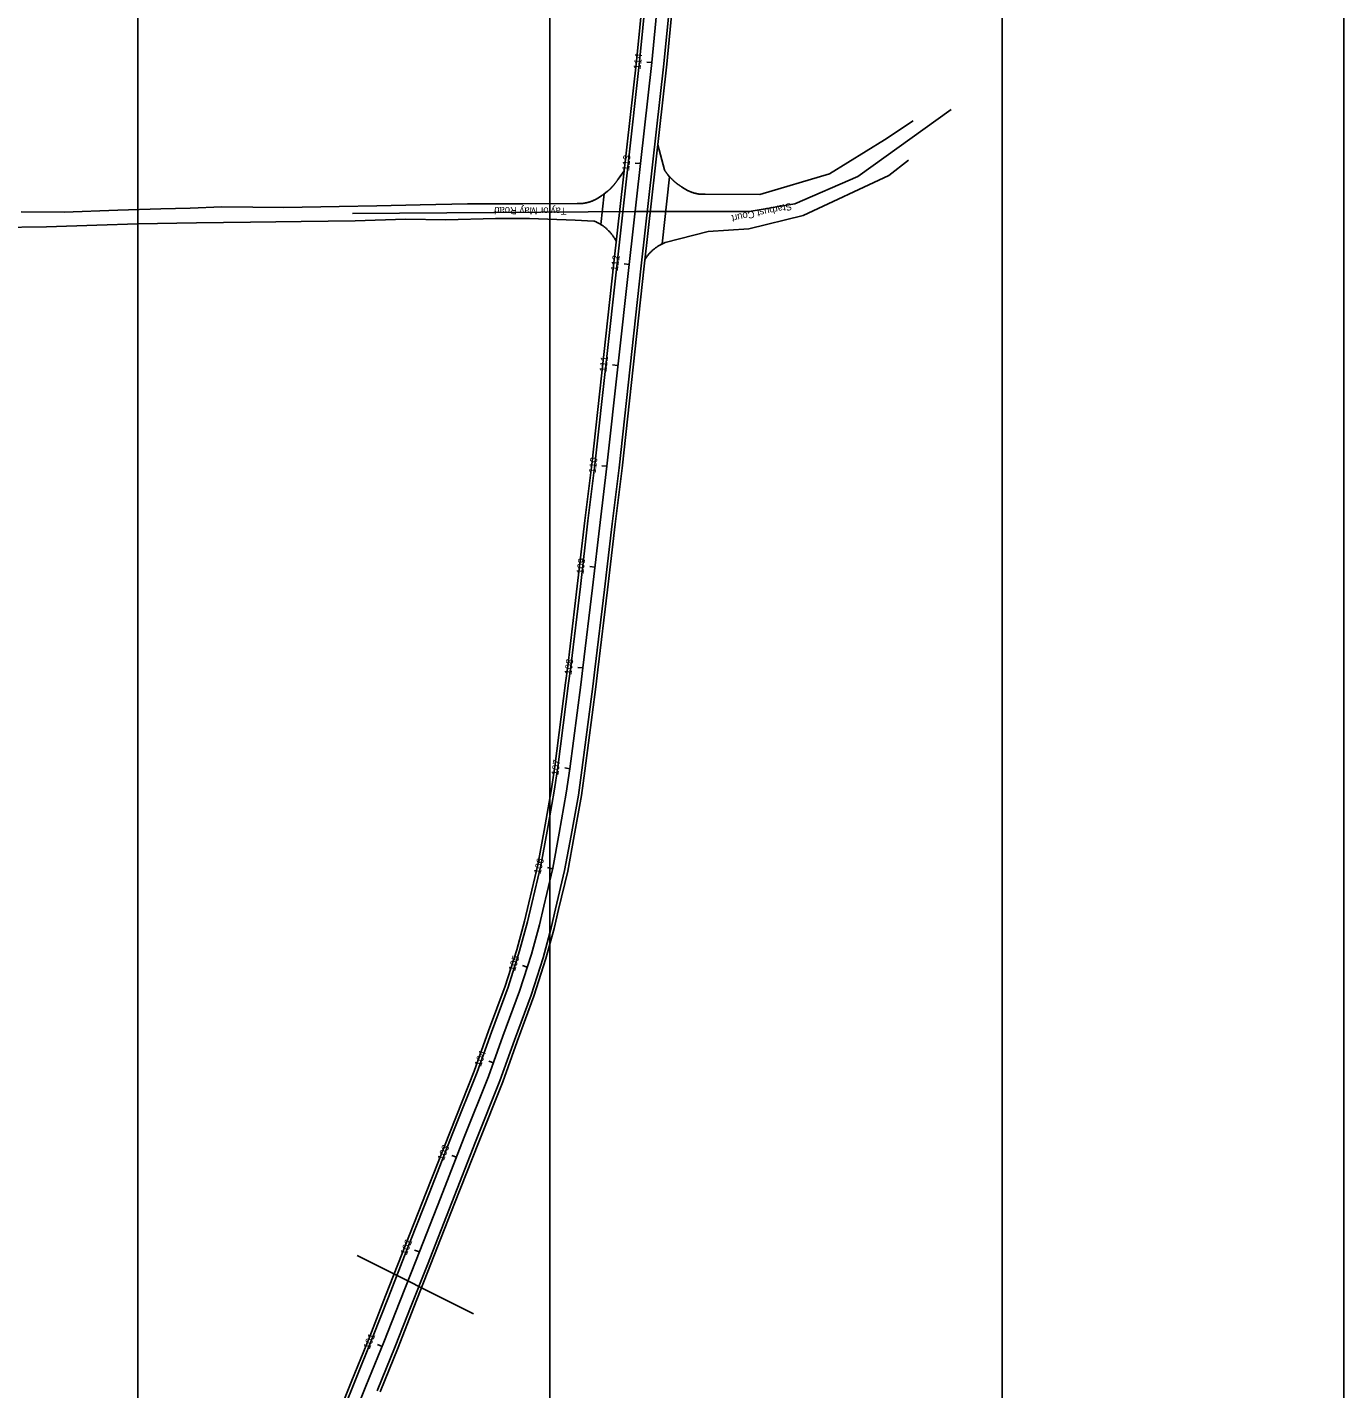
# Model space of a CAD drawing. Extents: x 2318076 to 2324211, y 613525 to 630327.
# Drawn here: x 2319710 to 2321006, y 624679 to 626020 of the extents above; entities that cross this region are included whole.
import ezdxf

# ---------------------------------------------------------------- set-up
doc = ezdxf.new("R2010")
doc.units = 0
for name, color, linetype in [('DR_P_Culvert', 7, 'Continuous'), ('GE_P_CL_50', 7, 'Continuous'), ('GE_X_CL_50', 7, 'Continuous'), ('PV_P_EOP', 7, 'Continuous'), ('PV_P_Shoulder', 7, 'Continuous'), ('RS_Raster1', 7, 'Continuous'), ('SC_Scratch3', 7, 'Continuous')]:
    doc.layers.add(name, color=color, linetype=linetype)

msp = doc.modelspace()

# ---------------------------------------------------------------- linework, layer by layer
at = {"layer": 'DR_P_Culvert'}
msp.add_line((2320034.8, 624810.3), (2320149.2, 624752.7), dxfattribs=at)
at = {"layer": 'GE_P_CL_50'}
for p, q in [((2320324.8, 625984.9), (2320319.9, 625985.4)), ((2320313.5, 625885.5), (2320308.5, 625885.9)), ((2320302.5, 625786.1), (2320297.6, 625786.8)), ((2320291.2, 625686.8), (2320286.2, 625687.3)), ((2320280.7, 625587.4), (2320275.7, 625588)), ((2320268.8, 625488.1), (2320263.8, 625488.6)), ((2320256.9, 625388.8), (2320251.9, 625389.4)), ((2320244.1, 625289.6), (2320239.1, 625290.3)), ((2320227.1, 625191.1), (2320222.2, 625192.2)), ((2320202.2, 625094.2), (2320197.5, 625095.8)), ((2320168.9, 625000), (2320164.2, 625001.7)), ((2320132.4, 624906.9), (2320127.8, 624908.7)), ((2320095.9, 624813.8), (2320091.2, 624815.6)), ((2320059.3, 624720.7), (2320054.6, 624722.6))]:
    msp.add_line(p, q, dxfattribs=at)
msp.add_lwpolyline([(2320021.9, 624628), (2320043.3, 624681.5), (2320061, 624725), (2320076.6, 624764.9), (2320092.6, 624805.5), (2320116.7, 624866.8), (2320140.2, 624926.6), (2320164.1, 624986.4), (2320178.2, 625026.2), (2320194.7, 625070.4), (2320206.2, 625106.8), (2320214.2, 625135.8), (2320218.4, 625154.2), (2320227.3, 625191.8), (2320233.6, 625226.1), (2320240.6, 625265.4), (2320244.1, 625289.6), (2320254.8, 625372.2), (2320256.9, 625388.8), (2320266.4, 625467.6), (2320273.9, 625532.1), (2320280.7, 625587.4), (2320302.5, 625786.1), (2320324.8, 625984.9), (2320334.4, 626084.4)], dxfattribs=at)
at = {"layer": 'GE_X_CL_50'}
msp.add_line((2320030.2, 625836.3), (2320308.4, 625838.2), dxfattribs=at)
msp.add_lwpolyline([(2320308.4, 625838.2), (2320420.7, 625838.2), (2320465.7, 625846), (2320527.8, 625872.6), (2320619.6, 625938.9)], dxfattribs=at)
at = {"layer": 'PV_P_EOP'}
for p, q in [((2320337.3, 625879.2), (2320330.9, 625904.1)), ((2320291.6, 625870), (2320297.8, 625878.4))]:
    msp.add_line(p, q, dxfattribs=at)
for points in [[(2320010.7, 624632.4), (2320032.2, 624686), (2320049.9, 624729.5), (2320065.5, 624769.3), (2320081.4, 624809.9), (2320105.5, 624871.2), (2320129, 624931), (2320152.8, 624990.6), (2320167, 625030.3), (2320183.3, 625074.3), (2320194.7, 625110.2), (2320202.5, 625138.7), (2320206.7, 625157), (2320215.5, 625194.3), (2320221.8, 625228.2), (2320228.8, 625267.4), (2320232.2, 625291.2), (2320242.9, 625373.7), (2320245, 625390.2), (2320254.5, 625469), (2320262, 625533.6), (2320268.7, 625588.7), (2320290.6, 625787.5), (2320312.9, 625986.1), (2320322.5, 626085.7)], [(2320054.4, 624677), (2320072.2, 624720.6), (2320087.8, 624760.5), (2320103.8, 624801.1), (2320127.8, 624862.4), (2320151.3, 624922.2), (2320175.3, 624982.1), (2320189.5, 625022.1), (2320206, 625066.5), (2320217.7, 625103.4), (2320225.8, 625132.9), (2320230, 625151.5), (2320239, 625189.3), (2320245.4, 625223.9), (2320252.5, 625263.5), (2320256, 625288), (2320266.7, 625370.6), (2320268.8, 625387.3), (2320278.3, 625466.2), (2320285.8, 625530.7), (2320292.6, 625586), (2320314.4, 625784.8), (2320336.8, 625983.6), (2320346.4, 626083.1)], [(2320342.4, 625872.4), (2320340.8, 625874.4), (2320340.7, 625874.5), (2320340.5, 625874.7), (2320340.4, 625874.8), (2320340.3, 625875), (2320340.2, 625875.1), (2320340.1, 625875.3), (2320340, 625875.4), (2320339.9, 625875.6), (2320339.8, 625875.7), (2320339.6, 625875.8), (2320339.5, 625876), (2320339.4, 625876.1), (2320339.3, 625876.3), (2320339.2, 625876.4), (2320339.1, 625876.6), (2320339, 625876.7), (2320338.9, 625876.9), (2320338.8, 625877), (2320338.7, 625877.2), (2320338.6, 625877.3), (2320338.5, 625877.5), (2320338.4, 625877.6), (2320338.2, 625877.8), (2320338.1, 625877.9), (2320338, 625878.1), (2320337.9, 625878.3), (2320337.8, 625878.4), (2320337.7, 625878.6), (2320337.6, 625878.7), (2320337.5, 625878.9), (2320337.4, 625879), (2320337.3, 625879.2)], [(2320278.1, 625855.6), (2320281, 625858), (2320281.2, 625858.1), (2320281.3, 625858.3), (2320281.5, 625858.4), (2320281.6, 625858.5), (2320281.7, 625858.6), (2320281.9, 625858.7), (2320282, 625858.9), (2320282.2, 625859), (2320282.3, 625859.1), (2320282.4, 625859.2), (2320282.6, 625859.4), (2320282.7, 625859.5), (2320282.8, 625859.6), (2320283, 625859.7), (2320283.1, 625859.9), (2320283.2, 625860), (2320283.4, 625860.1), (2320283.5, 625860.2), (2320283.7, 625860.4), (2320283.8, 625860.5), (2320283.9, 625860.6), (2320284, 625860.7), (2320284.2, 625860.9), (2320284.3, 625861), (2320284.4, 625861.1), (2320284.6, 625861.3), (2320284.7, 625861.4), (2320284.8, 625861.5), (2320285, 625861.7), (2320285.1, 625861.8), (2320285.2, 625861.9), (2320285.3, 625862.1), (2320285.5, 625862.2), (2320285.6, 625862.3), (2320285.7, 625862.5), (2320285.8, 625862.6), (2320286, 625862.7), (2320286.1, 625862.9), (2320286.2, 625863), (2320286.3, 625863.1), (2320286.5, 625863.3), (2320286.6, 625863.4), (2320286.7, 625863.6), (2320286.8, 625863.7), (2320287, 625863.8), (2320287.1, 625864), (2320287.2, 625864.1), (2320287.3, 625864.2), (2320287.4, 625864.4), (2320287.6, 625864.5), (2320287.7, 625864.7), (2320287.8, 625864.8), (2320287.9, 625865), (2320288, 625865.1), (2320288.1, 625865.2), (2320288.3, 625865.4), (2320288.4, 625865.5), (2320288.5, 625865.7), (2320288.6, 625865.8), (2320288.7, 625866), (2320288.8, 625866.1), (2320288.9, 625866.3), (2320289.1, 625866.4), (2320289.2, 625866.5), (2320289.3, 625866.7), (2320289.4, 625866.8), (2320289.5, 625867), (2320289.6, 625867.1), (2320289.7, 625867.3), (2320289.8, 625867.4), (2320289.9, 625867.6), (2320290, 625867.7), (2320290.1, 625867.9), (2320290.2, 625868), (2320290.4, 625868.2), (2320290.5, 625868.3), (2320290.6, 625868.5), (2320290.7, 625868.6), (2320290.8, 625868.8), (2320290.9, 625868.9), (2320291, 625869.1), (2320291.1, 625869.3), (2320291.2, 625869.4), (2320291.3, 625869.6), (2320291.4, 625869.7), (2320291.5, 625869.9), (2320291.6, 625870)], [(2320335, 625806.5), (2320342.4, 625872.4)], [(2320274.7, 625825.5), (2320278.1, 625855.6)], [(2320274.7, 625825.5), (2320276.8, 625824.1), (2320277.3, 625823.7), (2320277.9, 625823.2), (2320278.5, 625822.8), (2320279.1, 625822.3), (2320279.6, 625821.8), (2320280.2, 625821.4), (2320280.7, 625820.9), (2320281.2, 625820.4), (2320281.7, 625819.9), (2320282.2, 625819.4), (2320282.8, 625818.9), (2320283.2, 625818.3), (2320283.7, 625817.8), (2320284.2, 625817.2), (2320284.7, 625816.7), (2320285.1, 625816.1), (2320285.6, 625815.6), (2320286, 625815), (2320286.4, 625814.4), (2320286.8, 625813.8), (2320287.3, 625813.2), (2320287.6, 625812.6), (2320288, 625812), (2320290, 625808.8)], [(2320335, 625806.5), (2320331.5, 625804.4), (2320330.9, 625804), (2320330.3, 625803.6), (2320329.7, 625803.2), (2320329.1, 625802.8), (2320328.5, 625802.4), (2320327.9, 625802), (2320327.4, 625801.5), (2320326.8, 625801.1), (2320326.3, 625800.6), (2320325.7, 625800.1), (2320325.2, 625799.6), (2320324.6, 625799.1), (2320324.1, 625798.6), (2320323.6, 625798.1), (2320323.1, 625797.6), (2320322.6, 625797.1), (2320322.1, 625796.5), (2320321.7, 625796), (2320321.2, 625795.4), (2320320.7, 625794.9), (2320320.3, 625794.3), (2320319.9, 625793.7), (2320319.4, 625793.1), (2320319, 625792.5), (2320318.6, 625791.9), (2320318.2, 625791.3), (2320318.2, 625791.3)]]:
    msp.add_lwpolyline(points, dxfattribs=at)
at = {"layer": 'PV_P_Shoulder'}
for points in [[(2320007.9, 624633.5), (2320029.4, 624687.1), (2320047.1, 624730.6), (2320062.7, 624770.4), (2320102.7, 624872.3), (2320126.2, 624932.1), (2320150, 624991.7), (2320164.1, 625031.3), (2320180.5, 625075.3), (2320191.8, 625111.1), (2320199.6, 625139.4), (2320203.7, 625157.6), (2320212.6, 625194.9), (2320218.8, 625228.7), (2320225.8, 625267.8), (2320229.2, 625291.6), (2320239.9, 625374.1), (2320242, 625390.6), (2320251.5, 625469.4), (2320259, 625533.9), (2320265.8, 625589.1), (2320287.6, 625787.8), (2320309.9, 625986.4), (2320319.5, 626086)], [(2320057.2, 624675.9), (2320074.9, 624719.5), (2320090.6, 624759.4), (2320130.6, 624861.3), (2320154.1, 624921.1), (2320178.1, 624981.1), (2320192.3, 625021.1), (2320208.8, 625065.5), (2320220.6, 625102.6), (2320228.7, 625132.1), (2320233, 625150.9), (2320242, 625188.7), (2320248.3, 625223.4), (2320255.5, 625263.1), (2320258.9, 625287.6), (2320269.7, 625370.3), (2320271.8, 625386.9), (2320281.3, 625465.8), (2320288.8, 625530.4), (2320295.6, 625585.6), (2320317.4, 625784.5), (2320339.8, 625983.3), (2320349.3, 626082.7)]]:
    msp.add_lwpolyline(points, dxfattribs=at)
at = {"layer": 'RS_Raster1'}
for p, q in [((2320337.3, 625879.2), (2320330.9, 625904.1)), ((2320291.6, 625870), (2320295.4, 625875.2))]:
    msp.add_line(p, q, dxfattribs=at)
for points in [[(2320582.2, 625927.6), (2320554, 625909), (2320500, 625875.3), (2320431.2, 625854.9), (2320377.4, 625855.2)], [(2320353.7, 625863), (2320353.5, 625863.1), (2320353.4, 625863.2), (2320353.2, 625863.3), (2320353.1, 625863.4), (2320352.9, 625863.5), (2320352.8, 625863.6), (2320352.6, 625863.7), (2320352.5, 625863.8), (2320352.3, 625863.9), (2320352.1, 625864), (2320352, 625864.1), (2320351.8, 625864.2), (2320351.7, 625864.3), (2320351.5, 625864.4), (2320351.4, 625864.5), (2320351.2, 625864.6), (2320351.1, 625864.7), (2320350.9, 625864.8), (2320350.8, 625864.9), (2320350.6, 625865), (2320350.5, 625865.1), (2320350.3, 625865.2), (2320350.2, 625865.4), (2320350, 625865.5), (2320349.9, 625865.6), (2320349.8, 625865.7), (2320349.6, 625865.8), (2320349.5, 625865.9), (2320349.3, 625866), (2320349.2, 625866.1), (2320349, 625866.2), (2320348.9, 625866.4), (2320348.7, 625866.5), (2320348.6, 625866.6), (2320348.4, 625866.7), (2320348.3, 625866.8), (2320348.2, 625866.9), (2320348, 625867.1), (2320347.9, 625867.2), (2320347.7, 625867.3), (2320347.6, 625867.4), (2320347.5, 625867.5), (2320347.3, 625867.7), (2320347.2, 625867.8), (2320347, 625867.9), (2320346.9, 625868), (2320346.8, 625868.1), (2320346.6, 625868.3), (2320346.5, 625868.4), (2320346.3, 625868.5), (2320346.2, 625868.6), (2320346.1, 625868.8), (2320345.9, 625868.9), (2320345.8, 625869), (2320345.7, 625869.1), (2320345.5, 625869.3), (2320345.4, 625869.4), (2320345.3, 625869.5), (2320345.1, 625869.6), (2320345, 625869.8), (2320344.9, 625869.9), (2320344.7, 625870), (2320344.6, 625870.2), (2320344.5, 625870.3), (2320344.3, 625870.4), (2320344.2, 625870.5), (2320344.1, 625870.7), (2320344, 625870.8), (2320343.8, 625870.9), (2320343.7, 625871.1), (2320343.6, 625871.2), (2320343.4, 625871.3), (2320343.3, 625871.5), (2320343.2, 625871.6), (2320343.1, 625871.7), (2320342.9, 625871.9), (2320342.8, 625872), (2320342.7, 625872.2), (2320342.6, 625872.3), (2320342.4, 625872.4), (2320342.3, 625872.6), (2320342.2, 625872.7), (2320342.1, 625872.8), (2320342, 625873), (2320341.8, 625873.1), (2320341.7, 625873.3), (2320341.6, 625873.4), (2320341.5, 625873.5), (2320341.4, 625873.7), (2320341.2, 625873.8), (2320341.1, 625874), (2320341, 625874.1), (2320340.9, 625874.2), (2320340.8, 625874.4), (2320340.7, 625874.5), (2320340.5, 625874.7), (2320340.4, 625874.8), (2320340.3, 625875), (2320340.2, 625875.1), (2320340.1, 625875.3), (2320340, 625875.4), (2320339.9, 625875.6), (2320339.8, 625875.7), (2320339.6, 625875.8), (2320339.5, 625876), (2320339.4, 625876.1), (2320339.3, 625876.3), (2320339.2, 625876.4), (2320339.1, 625876.6), (2320339, 625876.7), (2320338.9, 625876.9), (2320338.8, 625877), (2320338.7, 625877.2), (2320338.6, 625877.3), (2320338.5, 625877.5), (2320338.4, 625877.6), (2320338.2, 625877.8), (2320338.1, 625877.9), (2320338, 625878.1), (2320337.9, 625878.3), (2320337.8, 625878.4), (2320337.7, 625878.6), (2320337.6, 625878.7), (2320337.5, 625878.9), (2320337.4, 625879), (2320337.3, 625879.2)], [(2320577.8, 625889), (2320558.4, 625873.7), (2320474.1, 625834.5), (2320420.6, 625821.3), (2320380.4, 625818.5), (2320338, 625807.7)], [(2320275.2, 625853.8), (2320275.4, 625853.9), (2320275.5, 625854), (2320275.7, 625854.1), (2320275.8, 625854.2), (2320276, 625854.3), (2320276.2, 625854.4), (2320276.3, 625854.5), (2320276.5, 625854.6), (2320276.6, 625854.7), (2320276.8, 625854.8), (2320276.9, 625854.9), (2320277.1, 625855), (2320277.2, 625855.1), (2320277.4, 625855.2), (2320277.5, 625855.3), (2320277.7, 625855.4), (2320277.8, 625855.6), (2320278, 625855.7), (2320278.1, 625855.8), (2320278.3, 625855.9), (2320278.4, 625856), (2320278.6, 625856.1), (2320278.7, 625856.2), (2320278.9, 625856.3), (2320279, 625856.4), (2320279.2, 625856.5), (2320279.3, 625856.6), (2320279.5, 625856.8), (2320279.6, 625856.9), (2320279.7, 625857), (2320279.9, 625857.1), (2320280, 625857.2), (2320280.2, 625857.3), (2320280.3, 625857.4), (2320280.5, 625857.6), (2320280.6, 625857.7), (2320280.8, 625857.8), (2320280.9, 625857.9), (2320281, 625858), (2320281.2, 625858.1), (2320281.3, 625858.3), (2320281.5, 625858.4), (2320281.6, 625858.5), (2320281.7, 625858.6), (2320281.9, 625858.7), (2320282, 625858.9), (2320282.2, 625859), (2320282.3, 625859.1), (2320282.4, 625859.2), (2320282.6, 625859.4), (2320282.7, 625859.5), (2320282.8, 625859.6), (2320283, 625859.7), (2320283.1, 625859.9), (2320283.2, 625860), (2320283.4, 625860.1), (2320283.5, 625860.2), (2320283.7, 625860.4), (2320283.8, 625860.5), (2320283.9, 625860.6), (2320284, 625860.7), (2320284.2, 625860.9), (2320284.3, 625861), (2320284.4, 625861.1), (2320284.6, 625861.3), (2320284.7, 625861.4), (2320284.8, 625861.5), (2320285, 625861.7), (2320285.1, 625861.8), (2320285.2, 625861.9), (2320285.3, 625862.1), (2320285.5, 625862.2), (2320285.6, 625862.3), (2320285.7, 625862.5), (2320285.8, 625862.6), (2320286, 625862.7), (2320286.1, 625862.9), (2320286.2, 625863), (2320286.3, 625863.1), (2320286.5, 625863.3), (2320286.6, 625863.4), (2320286.7, 625863.6), (2320286.8, 625863.7), (2320287, 625863.8), (2320287.1, 625864), (2320287.2, 625864.1), (2320287.3, 625864.2), (2320287.4, 625864.4), (2320287.6, 625864.5), (2320287.7, 625864.7), (2320287.8, 625864.8), (2320287.9, 625865), (2320288, 625865.1), (2320288.1, 625865.2), (2320288.3, 625865.4), (2320288.4, 625865.5), (2320288.5, 625865.7), (2320288.6, 625865.8), (2320288.7, 625866), (2320288.8, 625866.1), (2320288.9, 625866.3), (2320289.1, 625866.4), (2320289.2, 625866.5), (2320289.3, 625866.7), (2320289.4, 625866.8), (2320289.5, 625867), (2320289.6, 625867.1), (2320289.7, 625867.3), (2320289.8, 625867.4), (2320289.9, 625867.6), (2320290, 625867.7), (2320290.1, 625867.9), (2320290.2, 625868), (2320290.4, 625868.2), (2320290.5, 625868.3), (2320290.6, 625868.5), (2320290.7, 625868.6), (2320290.8, 625868.8), (2320290.9, 625868.9), (2320291, 625869.1), (2320291.1, 625869.3), (2320291.2, 625869.4), (2320291.3, 625869.6), (2320291.4, 625869.7), (2320291.5, 625869.9), (2320291.6, 625870)], [(2320251.5, 625846.1), (2320252.1, 625846.1), (2320252.7, 625846.1), (2320253.4, 625846.1), (2320254, 625846.1), (2320254.6, 625846.1), (2320255.2, 625846.1), (2320255.8, 625846.2), (2320256.5, 625846.2), (2320257.1, 625846.3), (2320257.7, 625846.4), (2320258.3, 625846.5), (2320258.9, 625846.6), (2320259.5, 625846.7), (2320260.1, 625846.8), (2320260.7, 625846.9), (2320261.3, 625847.1), (2320262, 625847.2), (2320262.6, 625847.4), (2320263.1, 625847.6), (2320263.7, 625847.8), (2320264.3, 625847.9), (2320264.9, 625848.1), (2320265.5, 625848.4), (2320266.1, 625848.6), (2320266.7, 625848.8), (2320267.2, 625849.1), (2320267.8, 625849.3), (2320268.4, 625849.6), (2320268.9, 625849.8), (2320269.5, 625850.1), (2320270, 625850.4), (2320270.6, 625850.7), (2320271.1, 625851), (2320271.6, 625851.3), (2320272.2, 625851.7), (2320272.7, 625852), (2320273.2, 625852.4), (2320273.7, 625852.7), (2320274.2, 625853.1), (2320274.7, 625853.4), (2320275.2, 625853.8)], [(2320377.4, 625855.2), (2320376.8, 625855.2), (2320376.2, 625855.2), (2320375.6, 625855.2), (2320374.9, 625855.2), (2320374.3, 625855.3), (2320373.7, 625855.3), (2320373.1, 625855.3), (2320372.5, 625855.4), (2320371.8, 625855.5), (2320371.2, 625855.5), (2320370.6, 625855.6), (2320370, 625855.7), (2320369.4, 625855.8), (2320368.8, 625856), (2320368.2, 625856.1), (2320367.6, 625856.2), (2320367, 625856.4), (2320366.4, 625856.5), (2320365.8, 625856.7), (2320365.2, 625856.9), (2320364.6, 625857.1), (2320364, 625857.3), (2320363.4, 625857.5), (2320362.8, 625857.7), (2320362.3, 625858), (2320361.7, 625858.2), (2320361.1, 625858.5), (2320360.6, 625858.7), (2320360, 625859), (2320359.4, 625859.3), (2320358.9, 625859.6), (2320358.3, 625859.9), (2320357.8, 625860.2), (2320357.3, 625860.5), (2320356.7, 625860.8), (2320356.2, 625861.2), (2320355.7, 625861.5), (2320355.2, 625861.9), (2320354.7, 625862.2), (2320354.2, 625862.6), (2320353.7, 625863)], [(2319703.6, 625838), (2319746, 625837.7), (2319798.8, 625839.7), (2319841.1, 625840.9), (2319870.1, 625841.6), (2319901.4, 625842.8), (2319962.5, 625842.2), (2320017, 625843.2), (2320054.1, 625843.9), (2320096.8, 625844.7), (2320143.4, 625845.9), (2320197.7, 625845.8), (2320251.5, 625846.1)], [(2319679.4, 625822.6), (2319728.6, 625823.1), (2319778.3, 625824.8), (2319818.6, 625826), (2319876.4, 625827.2), (2319929.7, 625827.7), (2319979.5, 625828.3), (2320032.8, 625829.2), (2320082.3, 625830.7), (2320121.9, 625830.2), (2320170.8, 625831.3), (2320204.4, 625831.4), (2320249.3, 625829.9), (2320267.9, 625828.9)], [(2320267.9, 625828.9), (2320268.6, 625828.7), (2320269.2, 625828.4), (2320269.9, 625828.1), (2320270.5, 625827.8), (2320271.2, 625827.5), (2320271.8, 625827.1), (2320272.5, 625826.8), (2320273.1, 625826.4), (2320273.7, 625826.1), (2320274.4, 625825.7), (2320275, 625825.3), (2320275.6, 625824.9), (2320276.2, 625824.5), (2320276.8, 625824.1), (2320277.3, 625823.7), (2320277.9, 625823.2), (2320278.5, 625822.8), (2320279.1, 625822.3), (2320279.6, 625821.8), (2320280.2, 625821.4), (2320280.7, 625820.9), (2320281.2, 625820.4), (2320281.7, 625819.9), (2320282.2, 625819.4), (2320282.8, 625818.9), (2320283.2, 625818.3), (2320283.7, 625817.8), (2320284.2, 625817.2), (2320284.7, 625816.7), (2320285.1, 625816.1), (2320285.6, 625815.6), (2320286, 625815), (2320286.4, 625814.4), (2320286.8, 625813.8), (2320287.3, 625813.2), (2320287.6, 625812.6), (2320288, 625812), (2320288.3, 625811.6)], [(2320338, 625807.7), (2320337.3, 625807.4), (2320336.6, 625807.1), (2320336, 625806.8), (2320335.3, 625806.5), (2320334.7, 625806.2), (2320334, 625805.9), (2320333.4, 625805.5), (2320332.8, 625805.2), (2320332.1, 625804.8), (2320331.5, 625804.4), (2320330.9, 625804), (2320330.3, 625803.6), (2320329.7, 625803.2), (2320329.1, 625802.8), (2320328.5, 625802.4), (2320327.9, 625802), (2320327.4, 625801.5), (2320326.8, 625801.1), (2320326.3, 625800.6), (2320325.7, 625800.1), (2320325.2, 625799.6), (2320324.6, 625799.1), (2320324.1, 625798.6), (2320323.6, 625798.1), (2320323.1, 625797.6), (2320322.6, 625797.1), (2320322.1, 625796.5), (2320321.7, 625796), (2320321.2, 625795.4), (2320320.7, 625794.9), (2320320.3, 625794.3), (2320319.9, 625793.7), (2320319.4, 625793.1), (2320319, 625792.5), (2320318.6, 625791.9), (2320318.2, 625791.3), (2320318.2, 625791.3)]]:
    msp.add_lwpolyline(points, dxfattribs=at)
at = {"layer": 'SC_Scratch3'}
for p, q in [((2319818.5, 614778.4), (2319818.5, 630327.2)), ((2320224.4, 614778.4), (2320224.4, 630327.2)), ((2320669.9, 614778.4), (2320669.9, 630327.2)), ((2321006.5, 614778.4), (2321006.5, 630327.2))]:
    msp.add_line(p, q, dxfattribs=at)

# ---------------------------------------------------------------- texts
at = {"layer": 'GE_P_CL_50'}
for s, rotation, p in [('114', 83.2927, (2320313.7, 625977.9)), ('113', 85.1931, (2320302.6, 625878.2)), ('Taylor May Road', 179.4616, (2320240.9, 625842.1)), ('Starbust Court', 191.7872, (2320462, 625846.9)), ('112', 82.4311, (2320291.3, 625779.4)), ('111', 84.0529, (2320280.2, 625680)), ('110', 83.0055, (2320269.5, 625580.3)), ('109', 83.3695, (2320257.6, 625481)), ('108', 82.8877, (2320245.7, 625381.8)), ('107', 81.9022, (2320232.7, 625282.6)), ('106', 76.6226, (2320215.2, 625185.3)), ('105', 72.3856, (2320190, 625089.5)), ('104', 70.4027, (2320156.5, 624995.7)), ('103', 68.5579, (2320119.9, 624903)), ('102', 68.5511, (2320083.3, 624809.9)), ('101', 67.8458, (2320046.8, 624717.3))]:
    msp.add_text(s, height=7, rotation=rotation, dxfattribs=at).set_placement(p)

doc.saveas('drawing.dxf')
